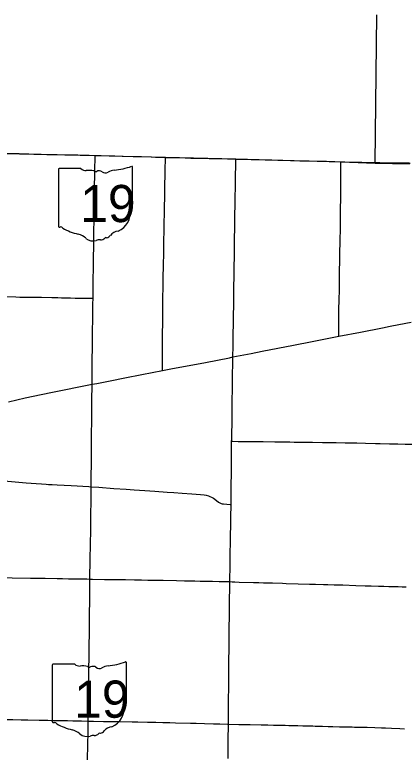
# Model space of a CAD drawing. Extents: x 9078 to 9739, y 4248 to 4966.
# Drawn here: x 9460 to 9533, y 4827.9 to 4966 of the extents above; entities that cross this region are included whole.
import ezdxf

# ---------------------------------------------------------------- set-up
doc = ezdxf.new("R2010")
doc.units = 0
for name, color, linetype in [('GM_X_Adjacent_County', 7, 'Continuous'), ('GM_X_County', 7, 'Continuous'), ('GM_X_County_Road', 7, 'Continuous'), ('GM_X_State_Route', 7, 'Continuous'), ('GM_X_State_Shield', 7, 'Continuous'), ('GM_X_Township_Road', 7, 'Continuous')]:
    doc.layers.add(name, color=color, linetype=linetype)

msp = doc.modelspace()

# ---------------------------------------------------------------- linework, layer by layer
at = {"layer": 'GM_X_Adjacent_County'}
msp.add_line((9527.58, 4938.18), (9527.85, 4965.97), dxfattribs=at)
at = {"layer": 'GM_X_County'}
msp.add_lwpolyline([(9450.03, 4940.19), (9460.88, 4939.95), (9475.07, 4939.63), (9488.24, 4939.29), (9501.44, 4938.97), (9521.15, 4938.43), (9527.58, 4938.18), (9534.01, 4938.03)], dxfattribs=at)
at = {"layer": 'GM_X_County_Road'}
for points in [[(9500.9, 4901.88), (9500.9, 4902.25), (9500.92, 4903.56), (9500.94, 4904.63), (9500.95, 4905.7), (9500.96, 4906.6), (9500.98, 4907.66), (9501, 4909.06), (9501.05, 4912.17), (9501.07, 4914.22), (9501.13, 4917.75), (9501.14, 4918.74), (9501.18, 4920.7), (9501.2, 4922.67), (9501.25, 4927.35), (9501.31, 4931.45), (9501.35, 4934.07), (9501.39, 4936.21), (9501.41, 4937.35), (9501.43, 4938.25), (9501.43, 4938.95)], [(9448.87, 4913.35), (9449.05, 4913.34), (9450.2, 4913.32), (9451.18, 4913.3), (9453.89, 4913.25), (9456.26, 4913.2), (9457.9, 4913.18), (9460.2, 4913.13), (9460.94, 4913.11), (9462.98, 4913.08), (9465.03, 4913.05), (9466.92, 4913.02), (9468.07, 4913), (9468.72, 4912.98), (9470.1, 4912.94), (9470.44, 4912.94), (9471.34, 4912.91), (9472.65, 4912.91), (9473.96, 4912.89), (9474.45, 4912.87), (9474.54, 4912.87), (9474.66, 4912.86)], [(9500.65, 4886.09), (9500.66, 4886.42), (9500.72, 4890.61), (9500.75, 4892.33), (9500.77, 4893.72), (9500.8, 4895.86), (9500.81, 4896.68), (9500.84, 4898.23), (9500.88, 4900.94), (9500.9, 4901.88)], [(9500.54, 4874.24), (9500.56, 4875.44), (9500.57, 4876.67), (9500.58, 4877.08), (9500.59, 4877.98), (9500.61, 4879.95), (9500.61, 4880.52), (9500.61, 4882.08), (9500.62, 4882.65), (9500.62, 4883.72), (9500.63, 4884.62), (9500.63, 4885.61), (9500.65, 4886.09)], [(9500.65, 4886.09), (9500.79, 4886.09), (9500.87, 4886.09), (9501.86, 4886.08), (9504.32, 4886.05), (9506.53, 4886.02), (9508.75, 4885.99), (9510.72, 4885.97), (9511.54, 4885.96), (9512.36, 4885.95), (9514.08, 4885.92), (9515.8, 4885.9), (9517.69, 4885.87), (9518.59, 4885.87), (9520.23, 4885.85), (9521.96, 4885.81), (9524.09, 4885.78), (9525.73, 4885.74), (9527.62, 4885.7), (9528.52, 4885.68), (9530.25, 4885.64), (9530.82, 4885.63)], [(9530.82, 4885.63), (9531.8, 4885.6), (9533.2, 4885.56), (9534.02, 4885.53), (9534.76, 4885.52), (9535.49, 4885.5), (9536.81, 4885.47), (9537.71, 4885.45), (9538.77, 4885.43), (9539.92, 4885.42), (9540.09, 4885.42)], [(9448.36, 4879.5), (9448.4, 4879.49), (9449.37, 4879.41), (9450.93, 4879.29), (9452.48, 4879.14), (9453.54, 4879.06), (9455.58, 4878.89), (9456.97, 4878.76), (9458.69, 4878.62), (9462.12, 4878.34), (9464, 4878.21), (9464.98, 4878.13), (9465.85, 4878.06)], [(9465.85, 4878.06), (9466.29, 4878.02), (9467.02, 4877.98), (9467.92, 4877.94), (9470.54, 4877.8), (9473.9, 4877.61), (9474.33, 4877.57)], [(9474.33, 4877.57), (9475.78, 4877.47), (9478.56, 4877.25), (9480.85, 4877.1), (9482.4, 4877), (9484.36, 4876.86), (9486.25, 4876.73), (9488.54, 4876.57), (9489.84, 4876.48), (9491.4, 4876.38), (9493.2, 4876.25), (9494.83, 4876.12), (9495.48, 4876.05), (9495.88, 4875.98), (9496.28, 4875.88), (9496.58, 4875.77), (9496.87, 4875.62), (9497.22, 4875.41), (9497.81, 4874.97), (9498.21, 4874.68), (9498.43, 4874.56), (9498.66, 4874.46), (9498.9, 4874.4), (9499.14, 4874.36), (9500.37, 4874.26), (9500.54, 4874.24)], [(9500.31, 4859.8), (9500.33, 4860.76), (9500.36, 4861.99), (9500.38, 4863.47), (9500.4, 4864.95), (9500.44, 4867.32), (9500.46, 4868.64), (9500.49, 4870.19), (9500.5, 4871.26), (9500.51, 4872.24), (9500.54, 4873.8), (9500.54, 4874.24)], [(9500.04, 4833.13), (9500.04, 4834.12), (9500.05, 4835.84), (9500.06, 4836.66), (9500.07, 4837.48), (9500.08, 4838.13), (9500.1, 4839.61), (9500.1, 4840.18), (9500.11, 4841.16), (9500.14, 4844.12), (9500.15, 4845.59), (9500.16, 4846.66), (9500.16, 4847.89), (9500.18, 4849.37), (9500.19, 4850.1), (9500.21, 4851.41), (9500.23, 4853.06), (9500.25, 4854.86), (9500.27, 4856.58), (9500.28, 4858.39), (9500.31, 4859.53), (9500.31, 4859.8)], [(9447.6, 4834.25), (9449.08, 4834.22), (9451.7, 4834.16), (9452.76, 4834.13), (9455.71, 4834.06), (9456.77, 4834.03), (9457.76, 4834.01), (9458.58, 4833.99), (9459.15, 4833.98), (9459.64, 4833.98), (9461.2, 4833.94), (9462.43, 4833.91), (9464.56, 4833.88), (9465.13, 4833.87), (9466.2, 4833.84), (9466.86, 4833.83), (9467.76, 4833.81), (9469.15, 4833.78), (9469.89, 4833.77), (9470.87, 4833.75), (9472.51, 4833.71), (9473.74, 4833.69)], [(9473.74, 4833.69), (9474.72, 4833.67), (9476.61, 4833.64), (9477.76, 4833.62), (9478.82, 4833.61), (9479.56, 4833.59), (9482.02, 4833.56), (9483.09, 4833.54), (9484.89, 4833.51), (9486.45, 4833.48), (9487.76, 4833.45), (9489.07, 4833.42), (9490.14, 4833.39), (9492.92, 4833.32), (9493.99, 4833.29), (9495.55, 4833.25), (9497.27, 4833.2), (9498.41, 4833.17), (9499.89, 4833.13), (9500.04, 4833.13)], [(9499.97, 4826.66), (9499.99, 4829.37), (9500, 4830.18), (9500.01, 4831), (9500.03, 4832.15), (9500.04, 4832.72), (9500.04, 4833.13)], [(9500.04, 4833.13), (9502.02, 4833.08), (9504.15, 4833.04), (9506.2, 4833), (9507.02, 4832.98), (9507.43, 4832.97), (9508.5, 4832.95), (9509.23, 4832.94), (9509.81, 4832.93), (9510.71, 4832.9), (9511.36, 4832.88), (9512.51, 4832.85), (9513.08, 4832.84), (9513.99, 4832.82), (9514.72, 4832.8), (9515.3, 4832.79), (9515.87, 4832.77), (9516.28, 4832.76), (9516.93, 4832.73), (9517.67, 4832.72), (9518.74, 4832.69), (9519.64, 4832.67), (9520.87, 4832.64), (9521.85, 4832.61), (9522.67, 4832.6), (9523.25, 4832.59), (9523.66, 4832.58), (9524.56, 4832.56), (9526.03, 4832.52), (9527.51, 4832.48), (9528.74, 4832.43), (9529.47, 4832.4), (9530.62, 4832.36), (9532.18, 4832.29), (9533.08, 4832.26)]]:
    msp.add_lwpolyline(points, dxfattribs=at)
at = {"layer": 'GM_X_State_Route'}
for points in [[(9474.5, 4896.77), (9474.5, 4896.96), (9474.52, 4899.26), (9474.53, 4900.41), (9474.53, 4901.47), (9474.55, 4903.52), (9474.59, 4906.48), (9474.62, 4909.18), (9474.64, 4911.81), (9474.66, 4912.86), (9474.69, 4914.93), (9474.71, 4916.9), (9474.73, 4918.04), (9474.78, 4920.18), (9474.82, 4922.88), (9474.84, 4924.61), (9474.88, 4928.22), (9474.92, 4929.77), (9474.93, 4930.76), (9474.96, 4932.97), (9475.03, 4936.83), (9475.06, 4939.45), (9475.06, 4939.63)], [(9521.15, 4938.45), (9521.85, 4938.41), (9524.08, 4938.38), (9525.06, 4938.36), (9526.26, 4938.32), (9527.71, 4938.29)], [(9527.71, 4938.29), (9527.74, 4938.29), (9528.41, 4938.28), (9531.44, 4938.26), (9533, 4938.25), (9533.56, 4938.24), (9533.8, 4938.23), (9533.86, 4938.23), (9533.97, 4938.2), (9534.05, 4938.16), (9534.1, 4938.13)], [(9458.82, 4893.48), (9461.94, 4894.2), (9463.46, 4894.53), (9466.76, 4895.2), (9468.93, 4895.64), (9472.31, 4896.33), (9474.5, 4896.77), (9475.37, 4896.94), (9477.86, 4897.44), (9480.6, 4897.97), (9483.82, 4898.59), (9487.69, 4899.33), (9489.22, 4899.63), (9495.75, 4900.85), (9500.26, 4901.75), (9500.9, 4901.88), (9504.29, 4902.54), (9506.38, 4902.95), (9512.26, 4904.11), (9515.72, 4904.77), (9518.22, 4905.27), (9520.77, 4905.76), (9524.82, 4906.55), (9528.93, 4907.35), (9530.38, 4907.63), (9531.99, 4907.95), (9534.32, 4908.4)], [(9473.59, 4825.09), (9473.67, 4828.79), (9473.72, 4832.07), (9473.74, 4833.69), (9473.78, 4836), (9473.8, 4837.65), (9473.83, 4840.11), (9473.85, 4841.83), (9473.88, 4843.31), (9473.91, 4845.85), (9473.98, 4852.17), (9474.05, 4857.83), (9474.09, 4860.28), (9474.15, 4864.06), (9474.19, 4866.69), (9474.24, 4869.56), (9474.26, 4871.69), (9474.32, 4875.55), (9474.33, 4877.57), (9474.34, 4878.75), (9474.38, 4882.68), (9474.4, 4885.88), (9474.44, 4891.46), (9474.46, 4893.6), (9474.5, 4896.77)]]:
    msp.add_lwpolyline(points, dxfattribs=at)
at = {"layer": 'GM_X_State_Shield'}
for p, q in [((9468.16, 4936.96), (9468.16, 4926.4)), ((9472.38, 4937.15), (9468.3, 4937.15)), ((9482.08, 4931.88), (9482.08, 4937.41)), ((9482.08, 4931.88), (9482.08, 4931.88)), ((9467.02, 4844.15), (9467.02, 4833.58)), ((9471.23, 4844.33), (9467.15, 4844.33)), ((9480.94, 4839.06), (9480.94, 4844.59)), ((9480.94, 4839.06), (9480.94, 4839.06))]:
    msp.add_line(p, q, dxfattribs=at)
for centre, radius, start, end in [((9468.32, 4936.99), 0.161, 98.1301, 188.1301), ((9473.35, 4938.37), 1.56, 231.6195, 271.1119), ((9473.86, 4931.21), 5.62, 80.4867, 94.9883), ((9475.14, 4937.04), 0.451, 219.7921, 297.1024), ((9475.8, 4935.82), 0.938, 54.4667, 119.1411), ((9477.01, 4937.49), 1.13, 233.8562, 294.8282), ((9479.01, 4933.92), 2.97, 97.3462, 120.7689), ((9477.12, 4951.55), 14.76, 275.8445, 288.9065), ((9481.93, 4937.43), 0.155, 351.8621, 97.738), ((9482.05, 4931.47), 0.24, 107.944, 210.337), ((9480.52, 4930.78), 1.44, 340.033, 23.6496), ((9481.92, 4931.86), 0.166, 289.6038, 7.7341), ((9482.64, 4929.57), 1.05, 136.8065, 186.9296), ((9477.95, 4928.86), 3.69, 292.3089, 8.9858), ((9468.32, 4926.37), 0.163, 171.9584, 258.3066), ((9468.35, 4927.45), 1.24, 267.339, 280.6039), ((9468.6, 4925.79), 0.448, 29.7484, 93.2717), ((9474.25, 4935.28), 10.66, 240.4129, 257.1985), ((9479.51, 4923.43), 2.02, 94.4031, 142.5768), ((9471.07, 4921.65), 3.34, 47.1842, 75.836), ((9474.68, 4925.73), 2.12, 230.7004, 286.2918), ((9476.06, 4924.94), 1.13, 268.777, 315.5493), ((9477.08, 4923.92), 0.318, 65.7517, 132.6484), ((9476.95, 4925.37), 1.19, 282.8732, 323.2771), ((9475.91, 4922.08), 1.74, 85.6951, 111.2099), ((9467.18, 4844.17), 0.161, 98.1301, 188.1301), ((9472.2, 4845.55), 1.56, 231.6195, 271.1119), ((9472.72, 4838.4), 5.62, 80.4867, 94.9883), ((9474, 4844.22), 0.451, 219.7921, 297.1024), ((9474.66, 4843), 0.938, 54.4667, 119.1411), ((9477.86, 4841.1), 2.97, 97.3462, 120.7689), ((9475.98, 4858.73), 14.76, 275.8445, 288.9065), ((9480.78, 4844.61), 0.155, 351.8621, 97.738), ((9475.87, 4844.68), 1.13, 233.8562, 294.8282), ((9480.9, 4838.66), 0.24, 107.944, 210.337), ((9479.38, 4837.96), 1.44, 340.033, 23.6496), ((9480.77, 4839.04), 0.166, 289.6038, 7.7341), ((9481.49, 4836.75), 1.05, 136.8065, 186.9296), ((9476.81, 4836.05), 3.69, 292.3089, 8.9858), ((9467.18, 4833.56), 0.163, 171.9584, 258.3066), ((9467.2, 4834.64), 1.24, 267.339, 280.6039), ((9467.46, 4832.97), 0.448, 29.7484, 93.2717), ((9473.11, 4842.46), 10.66, 240.4129, 257.1985), ((9469.93, 4828.83), 3.34, 47.1842, 75.836), ((9475.8, 4832.56), 1.19, 282.8732, 323.2771), ((9478.36, 4830.61), 2.02, 94.4031, 142.5768), ((9473.54, 4832.92), 2.12, 230.7004, 286.2918), ((9474.76, 4829.26), 1.74, 85.6951, 111.2099), ((9474.92, 4832.13), 1.13, 268.777, 315.5493), ((9475.94, 4831.1), 0.318, 65.7517, 132.6484)]:
    msp.add_arc(centre, radius, start, end, dxfattribs=at)
at = {"layer": 'GM_X_Township_Road'}
for points in [[(9450.22, 4940.17), (9451.3, 4940.16), (9452.3, 4940.14), (9453.77, 4940.11), (9455.69, 4940.07), (9457.42, 4940.03), (9459.59, 4939.99), (9460.83, 4939.96)], [(9460.83, 4939.96), (9462.62, 4939.92), (9463.54, 4939.89), (9464.2, 4939.87), (9464.94, 4939.85), (9466.01, 4939.83), (9466.79, 4939.81), (9467.93, 4939.79), (9469.49, 4939.76), (9471.79, 4939.72), (9473.02, 4939.69), (9473.92, 4939.66), (9475.06, 4939.63)], [(9475.06, 4939.63), (9476.21, 4939.59), (9477.77, 4939.56), (9478.75, 4939.53), (9480.15, 4939.49), (9482.2, 4939.44), (9483.76, 4939.4), (9485.56, 4939.35), (9486.4, 4939.32), (9487.45, 4939.28), (9488.22, 4939.26)], [(9487.73, 4909.71), (9487.73, 4909.94), (9487.74, 4911.09), (9487.76, 4912.49), (9487.77, 4913.39), (9487.79, 4914.54), (9487.83, 4917.25), (9487.86, 4918.48), (9487.92, 4921.92), (9487.95, 4923.73), (9487.98, 4925.37), (9488.02, 4927.18), (9488.04, 4928.57), (9488.11, 4933.25), (9488.18, 4936.78), (9488.23, 4939.16), (9488.22, 4939.26)], [(9488.22, 4939.26), (9488.27, 4939.26), (9489, 4939.25), (9491.95, 4939.16), (9493.02, 4939.13), (9493.84, 4939.11), (9494.58, 4939.1), (9495.4, 4939.09), (9496.46, 4939.07), (9498.27, 4939.03), (9501.43, 4938.95)], [(9501.43, 4938.95), (9504.3, 4938.88), (9506.91, 4938.81), (9508.21, 4938.78), (9509.3, 4938.74), (9510.23, 4938.72), (9511.66, 4938.68), (9513.46, 4938.64), (9515.2, 4938.62), (9516.69, 4938.58), (9517.49, 4938.56), (9518.43, 4938.54), (9519.97, 4938.49), (9521.15, 4938.45)], [(9520.77, 4905.76), (9520.77, 4905.93), (9520.77, 4906.75), (9520.76, 4907.73), (9520.76, 4908.72), (9520.77, 4910.03), (9520.77, 4910.93), (9520.79, 4912.4), (9520.84, 4914.62), (9520.85, 4915.35), (9520.87, 4916.34), (9520.9, 4918.3), (9520.92, 4919.53), (9520.95, 4921.09), (9520.96, 4922.07), (9520.99, 4922.73), (9521.01, 4923.63), (9521.02, 4924.28), (9521.03, 4925.35), (9521.06, 4926.74), (9521.05, 4927.31), (9521.06, 4928.38), (9521.07, 4929.94), (9521.09, 4931.25), (9521.1, 4932.31), (9521.12, 4934.03), (9521.14, 4936.08), (9521.15, 4938.45)], [(9487.69, 4899.33), (9487.68, 4899.51), (9487.67, 4899.93), (9487.68, 4901.65), (9487.69, 4903.05), (9487.7, 4904.52), (9487.7, 4906.25), (9487.72, 4908.22), (9487.73, 4909.71)], [(9448.09, 4860.71), (9448.27, 4860.71), (9450.81, 4860.68), (9452.45, 4860.65), (9454.59, 4860.6), (9456.39, 4860.58), (9458.11, 4860.56), (9459.51, 4860.54), (9462.95, 4860.48), (9465.66, 4860.43), (9467.92, 4860.4), (9468.94, 4860.38), (9470.09, 4860.35), (9472.3, 4860.32), (9472.79, 4860.31), (9473.53, 4860.3), (9474.09, 4860.28)], [(9474.09, 4860.28), (9474.59, 4860.26), (9476.81, 4860.23), (9477.93, 4860.22), (9479.32, 4860.2), (9479.92, 4860.19), (9480.75, 4860.18), (9482.46, 4860.15), (9483.76, 4860.12), (9484.91, 4860.11), (9486.3, 4860.08), (9487.78, 4860.06), (9490.32, 4860), (9491.8, 4859.97), (9493.77, 4859.94), (9494.75, 4859.91), (9497.05, 4859.87), (9498.28, 4859.84), (9499.51, 4859.82), (9500.25, 4859.8), (9500.31, 4859.8)], [(9500.31, 4859.8), (9500.74, 4859.78), (9501.23, 4859.76), (9502.05, 4859.73), (9504.75, 4859.64), (9505.33, 4859.63), (9505.74, 4859.62), (9506.64, 4859.6), (9507.38, 4859.58), (9508.28, 4859.56), (9510.16, 4859.51), (9510.9, 4859.48), (9513.12, 4859.41), (9515.24, 4859.35), (9516.39, 4859.32), (9517.87, 4859.28), (9518.69, 4859.25), (9519.84, 4859.22), (9521.48, 4859.18), (9523.94, 4859.11), (9525.66, 4859.05), (9526.81, 4859.02), (9528.2, 4858.97), (9529.19, 4858.93), (9530.09, 4858.92), (9530.91, 4858.9), (9531.89, 4858.87), (9532.63, 4858.85), (9533.37, 4858.82)]]:
    msp.add_lwpolyline(points, dxfattribs=at)

# ---------------------------------------------------------------- texts
at = {"layer": 'GM_X_State_Shield'}
for p in [(9472.28, 4927.14), (9471.14, 4834.32)]:
    msp.add_text('19', height=6.961, dxfattribs=at).set_placement(p)

doc.saveas('drawing.dxf')
